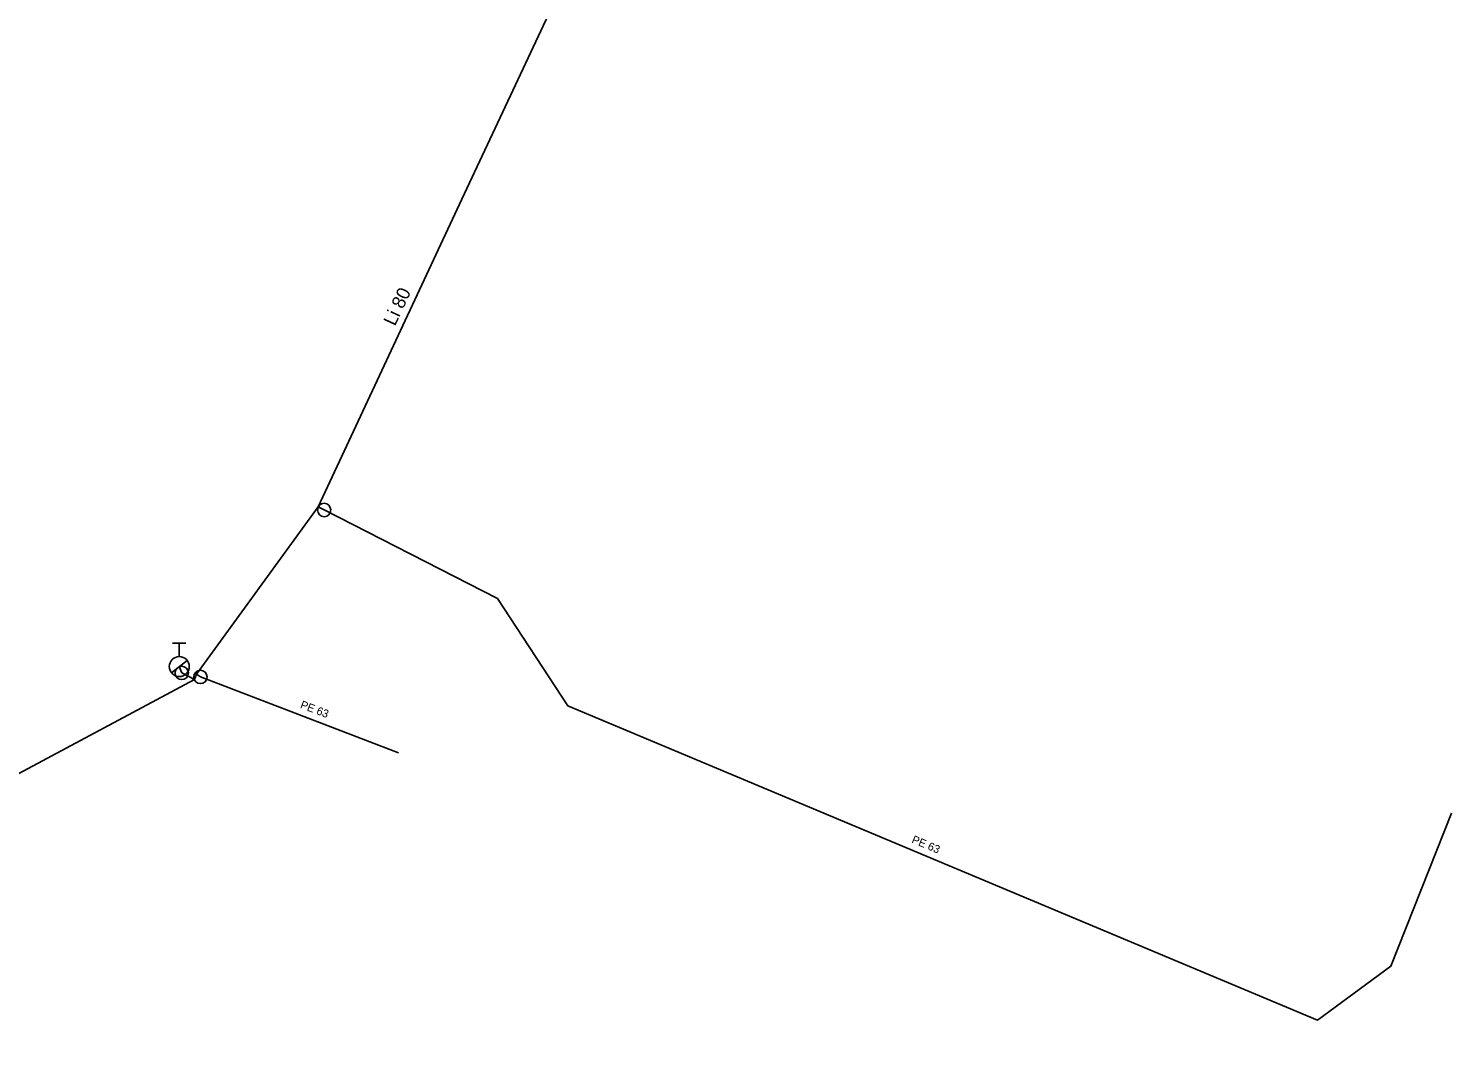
# Model space of a CAD drawing. Extents: x -770258 to -769930, y -1182247 to -1181932.
# Drawn here: x -770126.1 to -770072.8, y -1182103.6 to -1182064.8 of the extents above; entities that cross this region are included whole.
import ezdxf

# ---------------------------------------------------------------- set-up
doc = ezdxf.new("R2010")
doc.units = 0
for name, color, linetype in [('Hydranty', 7, 'Continuous'), ('Popis vodovodních řadů', 7, 'Continuous'), ('Vod přípojky-voda pitná', 7, 'Continuous'), ('Vodovodní řad', 7, 'Continuous'), ('Vodovodní šoupata', 7, 'Continuous')]:
    doc.layers.add(name, color=color, linetype=linetype)

msp = doc.modelspace()

# ---------------------------------------------------------------- linework, layer by layer
at = {"layer": 'Hydranty'}
for p, q in [((-770120.73, -1182087.855), (-770120.23, -1182087.855)), ((-770120.48, -1182088.355), (-770120.48, -1182087.855)), ((-770120.774, -1182088.961), (-770120.184, -1182088.498))]:
    msp.add_line(p, q, dxfattribs=at)
msp.add_circle((-770120.48, -1182088.73), 0.375, dxfattribs=at)
at = {"layer": 'Vod přípojky-voda pitná'}
for points in [[(-770115.27, -1182082.74), (-770115.05, -1182082.86), (-770108.55, -1182086.18), (-770105.92, -1182090.2), (-770077.82, -1182101.98), (-770075.06, -1182099.96), (-770072.79, -1182094.23)], [(-770119.84, -1182089.02), (-770119.69, -1182089.12), (-770112.26, -1182091.96)]]:
    msp.add_lwpolyline(points, dxfattribs=at)
at = {"layer": 'Vodovodní řad'}
for points in [[(-770119.91, -1182089.22), (-770119.84, -1182089.02), (-770115.27, -1182082.74), (-770109.89, -1182071.21), (-770105.68, -1182062.23)], [(-770120.39, -1182088.97), (-770120.48, -1182088.73)], [(-770119.91, -1182089.22), (-770120.39, -1182088.97)], [(-770146.83, -1182103.61), (-770119.91, -1182089.22)]]:
    msp.add_lwpolyline(points, dxfattribs=at)
at = {"layer": 'Vodovodní šoupata'}
for centre in [(-770115.05, -1182082.86), (-770120.39, -1182088.97), (-770119.69, -1182089.12)]:
    msp.add_circle(centre, 0.25, dxfattribs=at)

# ---------------------------------------------------------------- texts
at = {"layer": 'Popis vodovodních řadů'}
for s, height, rotation, p in [('Li 80', 0.5, 64.9858, (-770112.397, -1182075.991)), ('PE 63', 0.3, 339.0814, (-770115.97, -1182090.274)), ('PE 63', 0.3, 337.2557, (-770093.051, -1182095.324))]:
    msp.add_text(s, height=height, rotation=rotation, dxfattribs=at).set_placement(p)

doc.saveas('drawing.dxf')
